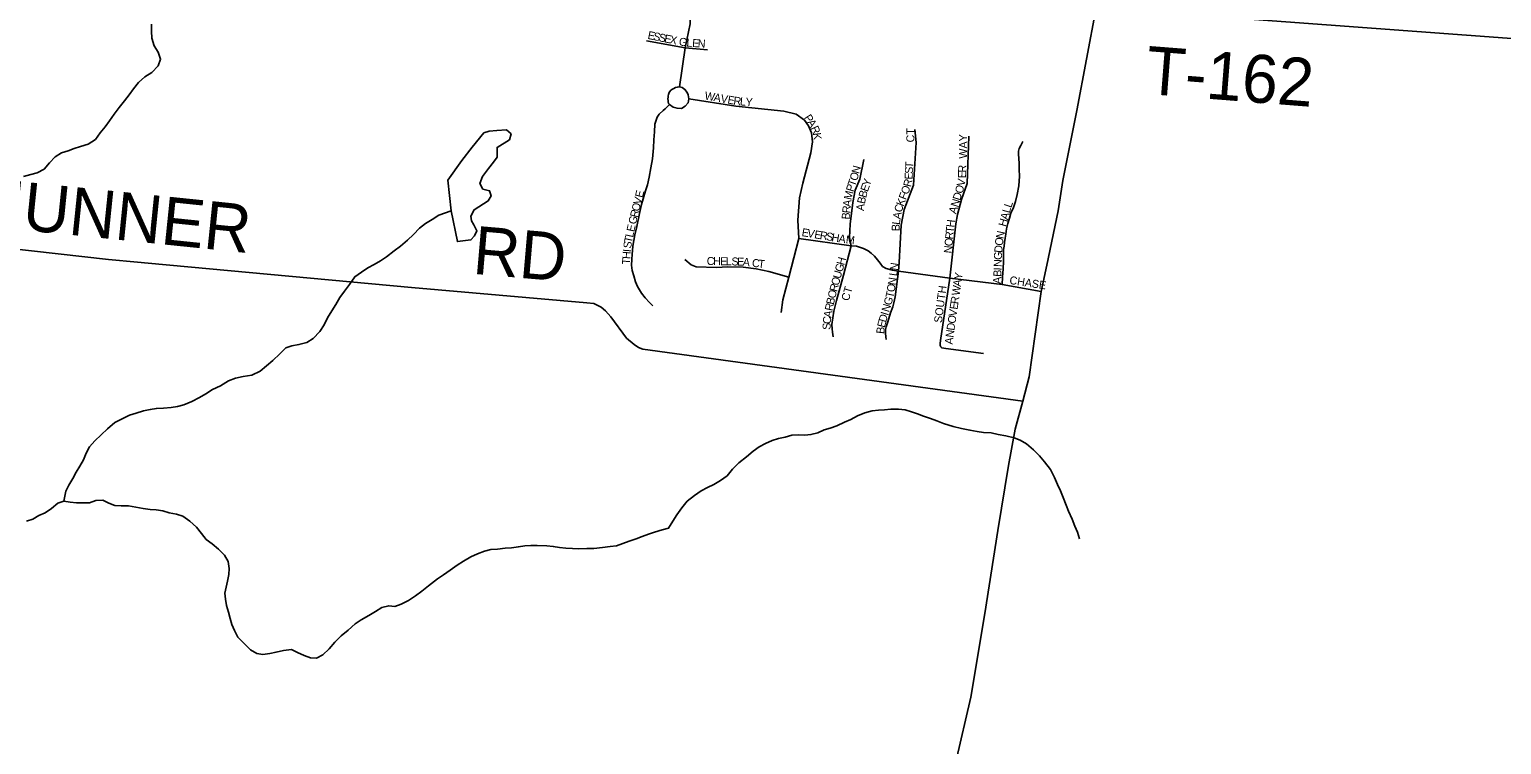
# Model space of a CAD drawing. Extents: x 0 to 34, y -4 to 22.
# Drawn here: x 5.794 to 7.021, y 15.668 to 16.264 of the extents above; entities that cross this region are included whole.
import ezdxf

# ---------------------------------------------------------------- set-up
doc = ezdxf.new("R2010")
doc.units = 0
for name, color, linetype in [('GM_X_County_Road', 7, 'Continuous'), ('GM_X_Minor_Lake', 7, 'Continuous'), ('GM_X_Minor_River', 7, 'Continuous'), ('GM_X_Township_Road', 7, 'Continuous'), ('GM_X_Township_Road_Text', 7, 'Continuous'), ('GM_X_Township_Subdivision', 7, 'Continuous'), ('GM_X_Township_Subdivision_Text', 7, 'Continuous')]:
    doc.layers.add(name, color=color, linetype=linetype)

msp = doc.modelspace()

# ---------------------------------------------------------------- linework, layer by layer
at = {"layer": 'GM_X_County_Road'}
msp.add_lwpolyline([(6.5663, 15.6539), (6.5786, 15.7078), (6.5903, 15.7773), (6.6012, 15.8464), (6.61, 15.9007), (6.6156, 15.9309), (6.6219, 15.9541), (6.6274, 15.9745), (6.6372, 16.0456), (6.6421, 16.0675), (6.6514, 16.1125), (6.6553, 16.1378), (6.6669, 16.1962), (6.6832, 16.2817)], dxfattribs=at)
at = {"layer": 'GM_X_Minor_Lake'}
for points in [[(6.173, 16.1777), (6.1633, 16.1656), (6.1547, 16.1546), (6.1428, 16.1381), (6.1456, 16.1126)], [(6.1456, 16.1126), (6.1509, 16.0871), (6.1621, 16.0884), (6.1652, 16.0918), (6.1672, 16.096), (6.1646, 16.1009), (6.1626, 16.1044), (6.1621, 16.1082), (6.1649, 16.1135), (6.1766, 16.1209), (6.1791, 16.1251), (6.1777, 16.1294), (6.1721, 16.1307), (6.1695, 16.1353), (6.1718, 16.1413), (6.1768, 16.1479), (6.1809, 16.1531), (6.184, 16.1573), (6.1841, 16.1614), (6.1839, 16.1654), (6.1943, 16.1718), (6.1957, 16.1768), (6.1918, 16.1801), (6.1838, 16.1795), (6.1773, 16.1789), (6.173, 16.1777)]]:
    msp.add_lwpolyline(points, dxfattribs=at)
at = {"layer": 'GM_X_Minor_River'}
for points in [[(5.8961, 16.2681), (5.896, 16.2623), (5.8964, 16.2564), (5.8982, 16.2499), (5.9016, 16.2448), (5.9036, 16.2389), (5.9016, 16.2333), (5.8962, 16.2278), (5.8905, 16.2241), (5.8851, 16.2194), (5.881, 16.2141), (5.8774, 16.2091), (5.8736, 16.2041), (5.8692, 16.1988), (5.8649, 16.193), (5.861, 16.1877), (5.8575, 16.1827), (5.8534, 16.1777), (5.8493, 16.1721), (5.8433, 16.1682), (5.8369, 16.1662), (5.8317, 16.1646), (5.8266, 16.1626), (5.8212, 16.1608), (5.8158, 16.1577), (5.8112, 16.1527), (5.8066, 16.1474), (5.8009, 16.1443), (5.7955, 16.1428), (5.7894, 16.1413)], [(6.1456, 16.1126), (6.1355, 16.109), (6.1298, 16.1054), (6.1244, 16.1022), (6.1193, 16.0981), (6.1144, 16.0928), (6.1092, 16.0883), (6.1035, 16.0833), (6.0983, 16.0794), (6.0918, 16.0744), (6.0867, 16.071), (6.0816, 16.0679), (6.0764, 16.0653), (6.071, 16.0617), (6.0654, 16.0577), (6.061, 16.0514), (6.0569, 16.0458), (6.053, 16.0406), (6.0497, 16.0347), (6.0464, 16.0294), (6.0428, 16.0236), (6.0398, 16.0178), (6.0362, 16.0122), (6.0308, 16.0064), (6.0254, 16.003), (6.0189, 16.0013), (6.013, 16.0003), (6.0079, 15.9985), (6.003, 15.9935), (5.997, 15.988), (5.9919, 15.9835), (5.9865, 15.9791), (5.9797, 15.9757), (5.9725, 15.9747), (5.966, 15.9732), (5.9601, 15.9712), (5.9534, 15.9668), (5.9469, 15.9639), (5.9412, 15.9603), (5.9361, 15.9571), (5.9296, 15.954), (5.9231, 15.9512), (5.9178, 15.9497), (5.9124, 15.949), (5.906, 15.9483), (5.9001, 15.9481), (5.895, 15.9471), (5.8893, 15.9461), (5.8832, 15.9441), (5.8778, 15.9426), (5.8705, 15.9389), (5.8654, 15.9363), (5.8594, 15.9311), (5.854, 15.9261), (5.8488, 15.9211), (5.8444, 15.9161), (5.8417, 15.9108), (5.8394, 15.9052), (5.8364, 15.8999), (5.8334, 15.8949), (5.8306, 15.8898), (5.8271, 15.8843), (5.8246, 15.8792), (5.8231, 15.871)], [(6.6692, 15.8394), (6.6674, 15.845), (6.6654, 15.8501), (6.663, 15.8558), (6.6599, 15.8625), (6.6582, 15.8676), (6.6556, 15.8738), (6.6535, 15.8795), (6.651, 15.8848), (6.6484, 15.8905), (6.645, 15.8972), (6.64, 15.9035), (6.6358, 15.9086), (6.6308, 15.9135), (6.625, 15.9187), (6.6197, 15.9217), (6.6147, 15.9236), (6.6078, 15.9254), (6.6014, 15.9265), (6.5955, 15.9277), (6.5893, 15.9281), (6.584, 15.9289), (6.5779, 15.9301), (6.5709, 15.9313), (6.564, 15.933), (6.5558, 15.9355), (6.5502, 15.9378), (6.5451, 15.9397), (6.5393, 15.9417), (6.5342, 15.9436), (6.5292, 15.9453), (6.5239, 15.947), (6.5183, 15.9474), (6.5121, 15.9475), (6.5067, 15.947), (6.5017, 15.9466), (6.4966, 15.9461), (6.4904, 15.9443), (6.4842, 15.9418), (6.4788, 15.9389), (6.4734, 15.9366), (6.4669, 15.9337), (6.4615, 15.9317), (6.4564, 15.9302), (6.4511, 15.9278), (6.4454, 15.9263), (6.4403, 15.9259), (6.435, 15.9262), (6.4296, 15.9258), (6.424, 15.9243), (6.4183, 15.923), (6.4132, 15.9215), (6.4076, 15.9189), (6.4024, 15.9161), (6.3973, 15.9124), (6.3919, 15.9079), (6.3854, 15.9027), (6.3802, 15.8974), (6.3756, 15.8919), (6.3701, 15.8882), (6.3645, 15.8848), (6.3593, 15.8823), (6.3539, 15.8794), (6.3485, 15.8757), (6.3423, 15.8708), (6.3379, 15.8652), (6.3338, 15.8594), (6.3305, 15.8541), (6.3269, 15.8485), (6.3216, 15.847), (6.3151, 15.845), (6.31, 15.8435), (6.3049, 15.8414), (6.2998, 15.8396), (6.2939, 15.8376), (6.2887, 15.8355), (6.2834, 15.8337), (6.2783, 15.833), (6.2718, 15.8323), (6.2646, 15.8316), (6.2587, 15.8315), (6.2518, 15.8313), (6.2467, 15.8316), (6.2413, 15.8317), (6.236, 15.8323), (6.2307, 15.8332), (6.2253, 15.8336), (6.2173, 15.834), (6.2122, 15.8341), (6.2071, 15.8336), (6.2018, 15.8329), (6.1959, 15.8319), (6.1908, 15.8317), (6.1843, 15.831), (6.1787, 15.8306), (6.1734, 15.8293), (6.1677, 15.827), (6.162, 15.8244), (6.1561, 15.821), (6.1507, 15.8177), (6.145, 15.8135)], [(6.145, 15.8135), (6.1393, 15.8096), (6.1342, 15.8062), (6.1269, 15.8004), (6.1212, 15.7959), (6.116, 15.792), (6.1103, 15.7881), (6.1041, 15.785), (6.0988, 15.7832), (6.0937, 15.7838), (6.088, 15.7823), (6.0826, 15.7789), (6.077, 15.7758), (6.0707, 15.7721), (6.0656, 15.7688), (6.0599, 15.7635), (6.0542, 15.7588), (6.0488, 15.7535), (6.0441, 15.748), (6.0387, 15.743), (6.0336, 15.7401), (6.0285, 15.7405), (6.0232, 15.7424), (6.0176, 15.7449), (6.0126, 15.7474), (6.0061, 15.7464), (5.9999, 15.7452), (5.9946, 15.7439), (5.9889, 15.7432), (5.9839, 15.7439), (5.9786, 15.7471), (5.9733, 15.7523), (5.9681, 15.7577), (5.9652, 15.7631), (5.9631, 15.7682), (5.9616, 15.7733), (5.9601, 15.7784), (5.9586, 15.7841), (5.9576, 15.7892), (5.9572, 15.7943), (5.9583, 15.7993), (5.9595, 15.8044), (5.9604, 15.8097), (5.9607, 15.8148), (5.96, 15.8207), (5.9569, 15.8258), (5.9519, 15.831), (5.9466, 15.8353), (5.9416, 15.8389), (5.9377, 15.844), (5.9335, 15.8492), (5.9279, 15.8541), (5.9221, 15.8584), (5.9168, 15.8601), (5.9109, 15.8613), (5.9056, 15.8627), (5.9, 15.8636), (5.8949, 15.864), (5.8891, 15.8649), (5.8829, 15.866), (5.8768, 15.8669), (5.8709, 15.867), (5.8656, 15.8674), (5.8605, 15.8691), (5.8555, 15.8718), (5.8498, 15.8714), (5.8445, 15.8696), (5.8391, 15.8694), (5.8335, 15.8695), (5.8282, 15.8701), (5.8231, 15.871), (5.818, 15.8692), (5.8128, 15.8647), (5.8074, 15.8613), (5.8023, 15.859), (5.7972, 15.8559), (5.792, 15.8541)]]:
    msp.add_lwpolyline(points, dxfattribs=at)
at = {"layer": 'GM_X_Township_Road'}
for points in [[(6.6832, 16.2817), (7.1083, 16.2502), (7.1211, 16.251), (7.1481, 16.2642), (7.1635, 16.2712), (7.1769, 16.2821), (7.1961, 16.3067), (7.2049, 16.3176), (7.2416, 16.3343), (7.2537, 16.3385), (7.356, 16.3193)], [(5.3313, 16.1294), (5.4166, 16.1207), (5.5632, 16.1052), (5.6897, 16.0913), (5.8603, 16.072), (5.8844, 16.0698)], [(5.8844, 16.0698), (5.8932, 16.069), (6.1128, 16.0487), (6.2588, 16.0361), (6.2645, 16.0354), (6.2706, 16.0323), (6.2742, 16.0294), (6.2788, 16.0243), (6.2919, 16.0065), (6.2981, 16.0012), (6.3019, 15.9989), (6.3053, 15.9975), (6.6219, 15.9541)]]:
    msp.add_lwpolyline(points, dxfattribs=at)
at = {"layer": 'GM_X_Township_Subdivision'}
for points in [[(6.3359, 16.216), (6.3407, 16.2485), (6.3447, 16.2684), (6.3451, 16.276), (6.3445, 16.2817), (6.3424, 16.2873), (6.3397, 16.2912), (6.3356, 16.2941), (6.3284, 16.2975), (6.3133, 16.2997), (6.3055, 16.3008)], [(6.3084, 16.2541), (6.3407, 16.2485), (6.3594, 16.2467)], [(6.4207, 16.0281), (6.4221, 16.0385), (6.427, 16.0575), (6.4353, 16.0896), (6.4344, 16.1048), (6.4358, 16.1234), (6.4387, 16.1357), (6.4455, 16.1608), (6.4467, 16.17), (6.4458, 16.1777), (6.4433, 16.1833), (6.4401, 16.188), (6.4331, 16.193), (6.423, 16.1955), (6.3828, 16.1998), (6.3437, 16.2058), (6.3431, 16.2092), (6.3422, 16.2113), (6.3405, 16.2138), (6.3382, 16.2153), (6.3359, 16.216), (6.3342, 16.2157), (6.3325, 16.2153), (6.3312, 16.2145), (6.33, 16.2139), (6.3286, 16.213), (6.3278, 16.2121), (6.3274, 16.2111), (6.327, 16.2102), (6.3268, 16.2094), (6.3266, 16.2084), (6.3264, 16.2073), (6.3263, 16.206), (6.3264, 16.2046), (6.3265, 16.2033), (6.3268, 16.202), (6.3277, 16.2012), (6.3306, 16.199), (6.334, 16.198), (6.3376, 16.1979), (6.3407, 16.1998), (6.3431, 16.2026), (6.3437, 16.2058)], [(6.3138, 16.0335), (6.3109, 16.0364), (6.3073, 16.0401), (6.3043, 16.0442), (6.3009, 16.0497), (6.2993, 16.0536), (6.2979, 16.0586), (6.2966, 16.063), (6.2959, 16.0673), (6.2961, 16.0721), (6.2964, 16.0765), (6.2968, 16.0797), (6.2971, 16.0833), (6.2986, 16.0927), (6.3003, 16.0997), (6.3027, 16.1105), (6.3044, 16.118), (6.3056, 16.1227), (6.3077, 16.1292), (6.3092, 16.1343), (6.3107, 16.1407), (6.3121, 16.1485), (6.3135, 16.1559), (6.3143, 16.1652), (6.3147, 16.1717), (6.315, 16.1784), (6.3155, 16.1847), (6.3172, 16.1905), (6.3189, 16.1931), (6.3224, 16.1963), (6.3241, 16.1977), (6.3277, 16.2012)], [(6.5185, 16.0624), (6.5189, 16.0695), (6.5206, 16.1008), (6.5231, 16.1137), (6.531, 16.1341), (6.5331, 16.1696), (6.5321, 16.1803)], [(6.5612, 16.0565), (6.5663, 16.1017), (6.5675, 16.1095), (6.5709, 16.122), (6.5756, 16.1355), (6.5769, 16.1749)], [(6.6047, 16.0514), (6.6051, 16.0573), (6.6056, 16.0643), (6.6058, 16.0707), (6.606, 16.0766), (6.606, 16.0804), (6.6064, 16.0831), (6.6066, 16.0863), (6.6072, 16.0898), (6.6078, 16.0932), (6.6085, 16.0976), (6.6095, 16.1022), (6.611, 16.1066), (6.6121, 16.1106), (6.6141, 16.1154), (6.6158, 16.1205), (6.6173, 16.1263), (6.6186, 16.1335), (6.6192, 16.1414), (6.619, 16.1471), (6.619, 16.1521), (6.6186, 16.1561), (6.6183, 16.1599), (6.6185, 16.1622), (6.619, 16.1645), (6.6202, 16.167), (6.6219, 16.1704)], [(6.479, 16.0836), (6.4776, 16.0903), (6.4781, 16.1014), (6.4803, 16.1195), (6.4824, 16.1299), (6.4861, 16.1389), (6.4894, 16.1553)], [(6.4353, 16.0896), (6.479, 16.0836), (6.4835, 16.0833), (6.4893, 16.0812), (6.4931, 16.0794), (6.4956, 16.0775), (6.4984, 16.0749), (6.501, 16.0718), (6.5032, 16.0691), (6.5051, 16.0663), (6.508, 16.0647), (6.5133, 16.0632), (6.5185, 16.0624), (6.5612, 16.0565), (6.6047, 16.0514), (6.6372, 16.0456)], [(6.464, 16.0078), (6.4633, 16.0116), (6.4631, 16.0143), (6.4629, 16.0181), (6.4637, 16.0235), (6.4646, 16.0292), (6.4667, 16.038), (6.4725, 16.0592), (6.479, 16.0836)], [(6.3405, 16.0721), (6.3456, 16.0676), (6.3499, 16.0661), (6.3669, 16.0655), (6.3762, 16.066), (6.3891, 16.0658), (6.3998, 16.0644), (6.4103, 16.0621), (6.427, 16.0575)], [(6.5082, 16.0056), (6.5078, 16.0076), (6.5076, 16.0108), (6.5076, 16.0137), (6.5082, 16.016), (6.5091, 16.0194), (6.5103, 16.0231), (6.5118, 16.0277), (6.5137, 16.0326), (6.5145, 16.0359), (6.5156, 16.041), (6.5185, 16.0624)], [(6.5891, 15.9938), (6.5578, 15.998), (6.5545, 15.9985), (6.5538, 15.9994), (6.5532, 16.0006), (6.5532, 16.0023), (6.5535, 16.0047), (6.5612, 16.0565)]]:
    msp.add_lwpolyline(points, dxfattribs=at)

# ---------------------------------------------------------------- texts
at = {"layer": 'GM_X_Township_Road_Text'}
for s, rotation, p in [('T-162', 355.5146, (6.7234, 16.2101)), ('NUNNER', 354.1259, (5.7492, 16.1008)), ('RD', 355.0738, (6.1629, 16.0603))]:
    msp.add_text(s, height=0.04, rotation=rotation, dxfattribs=at).set_placement(p)
at = {"layer": 'GM_X_Township_Subdivision_Text'}
for s, rotation, p in [('E', 348.5293, (6.309, 16.2559)), ('S', 348.5119, (6.3136, 16.255)), ('S', 348.536, (6.3182, 16.254)), ('E', 348.5293, (6.3228, 16.2531)), ('X', 348.5143, (6.3274, 16.2522)), ('G', 349.8087, (6.335, 16.2506)), ('L', 355.1896, (6.3415, 16.2495)), ('E', 356.1525, (6.3463, 16.2491)), ('N', 356.1873, (6.351, 16.2488)), ('W', 349.9628, (6.3565, 16.2055)), ('A', 349.9591, (6.364, 16.2041)), ('V', 349.9591, (6.3698, 16.2031)), ('E', 349.9493, (6.3756, 16.2021)), ('R', 352.9967, (6.3806, 16.2012)), ('L', 355.5188, (6.3861, 16.2005)), ('Y', 355.6123, (6.3908, 16.2002)), ('P', 302.6367, (6.4394, 16.1903)), ('A', 302.6651, (6.442, 16.1863)), ('R', 294.3817, (6.445, 16.1816)), ('K', 277.0329, (6.4471, 16.1773)), ('CT', 90, (6.5316, 16.1696)), ('WAY', 90, (6.5756, 16.1561)), ('T', 86.9987, (6.5306, 16.148)), ('O', 72.9826, (6.4838, 16.1371)), ('N', 75.604, (6.4856, 16.1431)), ('E', 87.466, (6.5301, 16.1386)), ('S', 86.9929, (6.5303, 16.1433)), ('E', 88.2235, (6.5746, 16.1397)), ('R', 87.9598, (6.5747, 16.1444)), ('E', 75.7329, (6.3052, 16.1231)), ('M', 77.1037, (6.4792, 16.1213)), ('P', 72.8611, (6.4808, 16.128)), ('T', 70.7357, (6.4821, 16.1324)), ('B', 74.1847, (6.4913, 16.123)), ('E', 70.563, (6.4927, 16.128)), ('Y', 72.1769, (6.4944, 16.1326)), ('F', 68.4269, (6.5245, 16.1213)), ('O', 68.4453, (6.5262, 16.1257)), ('R', 76.661, (6.5287, 16.1321)), ('O', 72.8187, (6.5715, 16.1264)), ('V', 79.4775, (6.5734, 16.1328)), ('O', 75.7093, (6.3023, 16.1117)), ('V', 75.7093, (6.3037, 16.1174)), ('R', 85.3312, (6.4781, 16.1104)), ('A', 82.349, (6.4785, 16.1156)), ('A', 83.5391, (6.4896, 16.1123)), ('B', 78.0138, (6.4903, 16.118)), ('C', 75.1155, (6.5211, 16.1109)), ('K', 68.8966, (6.5224, 16.1159)), ('N', 72.8024, (6.568, 16.1152)), ('D', 72.8187, (6.5697, 16.1208)), ('L', 71.0554, (6.6123, 16.1147)), ('G', 75.9797, (6.2996, 16.1009)), ('R', 75.7459, (6.301, 16.1066)), ('B', 85.3312, (6.4776, 16.1052)), ('L', 82.1905, (6.5194, 16.1007)), ('A', 79.5388, (6.5201, 16.1053)), ('H', 82.9238, (6.5648, 16.0986)), ('A', 72.8233, (6.5663, 16.1096)), ('H', 74.5379, (6.6079, 16.099)), ('A', 74.5321, (6.6095, 16.1046)), ('L', 74.1747, (6.611, 16.1103)), ('T', 78.3364, (6.2962, 16.0855)), ('L', 77.8594, (6.2972, 16.0901)), ('E', 77.6401, (6.2982, 16.0947)), ('E', 350.5871, (6.4374, 16.0917)), ('V', 350.5808, (6.4421, 16.0909)), ('E', 350.5601, (6.4479, 16.0899)), ('R', 350.6018, (6.4525, 16.0892)), ('S', 350.5871, (6.4577, 16.0883)), ('H', 350.5808, (6.4623, 16.0875)), ('A', 350.5592, (6.4681, 16.0866)), ('M', 353.2231, (6.4742, 16.0856)), ('B', 88.1539, (6.5193, 16.0956)), ('R', 84.4537, (6.5638, 16.0887)), ('T', 84.4444, (6.5643, 16.094)), ('N', 78.4929, (6.6059, 16.0889)), ('I', 85.6683, (6.2954, 16.0781)), ('S', 82.1327, (6.2956, 16.081)), ('N', 84.4612, (6.5627, 16.077)), ('O', 84.4612, (6.5633, 16.0829)), ('D', 86.4128, (6.6048, 16.0775)), ('O', 81.6443, (6.6051, 16.0832)), ('T', 85.6516, (6.2946, 16.0676)), ('H', 85.6573, (6.2949, 16.0723)), ('C', 358.8586, (6.3586, 16.0676)), ('H', 358.8668, (6.3639, 16.0675)), ('E', 358.876, (6.3698, 16.0674)), ('L', 358.8526, (6.3745, 16.0673)), ('S', 358.8648, (6.3792, 16.0672)), ('E', 358.1418, (6.3838, 16.0671)), ('A', 354.3525, (6.3884, 16.067)), ('C', 352.8659, (6.396, 16.0662)), ('T', 352.8869, (6.4012, 16.0655)), ('G', 74.6673, (6.4716, 16.0612)), ('H', 74.6673, (6.4731, 16.0669)), ('N', 81.5792, (6.5178, 16.0626)), ('N', 87.8085, (6.6043, 16.0658)), ('G', 87.7924, (6.6045, 16.0717)), ('O', 74.6673, (6.4685, 16.0499)), ('U', 74.6673, (6.47, 16.0556)), ('N', 81.5792, (6.516, 16.0504)), ('L', 81.5755, (6.5171, 16.058)), ('A', 81.5568, (6.5703, 16.0492)), ('Y', 81.5568, (6.5712, 16.055)), ('A', 87.7924, (6.6038, 16.0517)), ('B', 87.8073, (6.604, 16.0576)), ('I', 87.7705, (6.6042, 16.0629)), ('CHASE', 351.3478, (6.6105, 16.0518)), ('O', 75.1685, (6.4656, 16.0392)), ('R', 74.6618, (6.4671, 16.0448)), ('CT', 73.6056, (6.4769, 16.0371)), ('T', 77.9257, (6.514, 16.0396)), ('O', 81.4996, (6.5151, 16.0446)), ('SOUTH', 82.5722, (6.5545, 16.019)), ('W', 81.5525, (6.5692, 16.0417)), ('R', 78.6805, (6.4634, 16.0289)), ('B', 77.6134, (6.4645, 16.0341)), ('N', 73.496, (6.5105, 16.0278)), ('G', 73.4661, (6.5122, 16.0334)), ('V', 81.5568, (6.5666, 16.0243)), ('E', 81.5511, (6.5675, 16.0301)), ('R', 81.5659, (6.5682, 16.0347)), ('S', 89.2077, (6.4618, 16.0135)), ('C', 83.9173, (6.4618, 16.0181)), ('A', 79.6502, (6.4624, 16.0232)), ('E', 75.2745, (6.5069, 16.0149)), ('D', 73.4871, (6.508, 16.0193)), ('I', 73.4724, (6.5097, 16.025)), ('D', 81.5978, (6.5649, 16.0126)), ('O', 81.5546, (6.5658, 16.0184)), ('B', 84.0647, (6.5064, 16.0099)), ('A', 85.0984, (6.5636, 16.0011)), ('N', 82.1079, (6.5641, 16.0068))]:
    msp.add_text(s, height=0.00667, rotation=rotation, dxfattribs=at).set_placement(p)

doc.saveas('drawing.dxf')
